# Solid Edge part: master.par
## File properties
Author: Deepak Maini
Template: Normal.par
Last saved by: Robert a Rhodes jr
Revision: 1
Application: Solid Edge
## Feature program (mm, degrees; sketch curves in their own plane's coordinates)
body "unnamed Body 1"
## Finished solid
Body 1: solid body, 75 faces, 214 edges, 140 vertices.
  Faces by surface: cylinder 56, plane 19
  Edges by curve: circle 102, line 100, spline 12
Bounding box of the edges (mm): 7327.900 x 1778.000 x 2844.800, from (-1244.6, -355.6, -1422.4) to (6083.3, 1422.4, 1422.4).
Cylindrical faces by radius (mm): R152.4 x20, R304.8 x2, R330.2 x8, R444.5 x2, R635 x2, R660.4 x2, R800.1 x6, R1473.2 x4, R1828.8 x6, R1981.2 x4
Planar faces by outward normal: +y 5, +z 2, -x 1, -y 5, -z 2, oblique 4
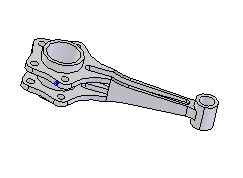
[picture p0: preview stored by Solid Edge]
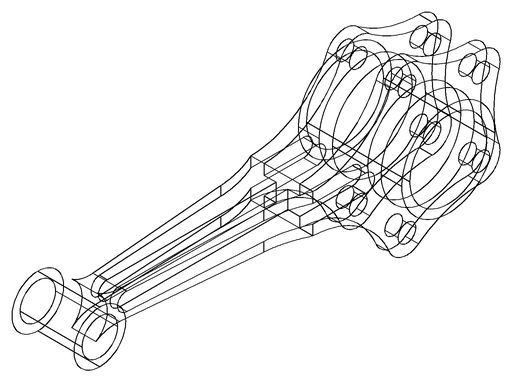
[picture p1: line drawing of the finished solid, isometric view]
